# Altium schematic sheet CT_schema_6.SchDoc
size 368 x 245 mm
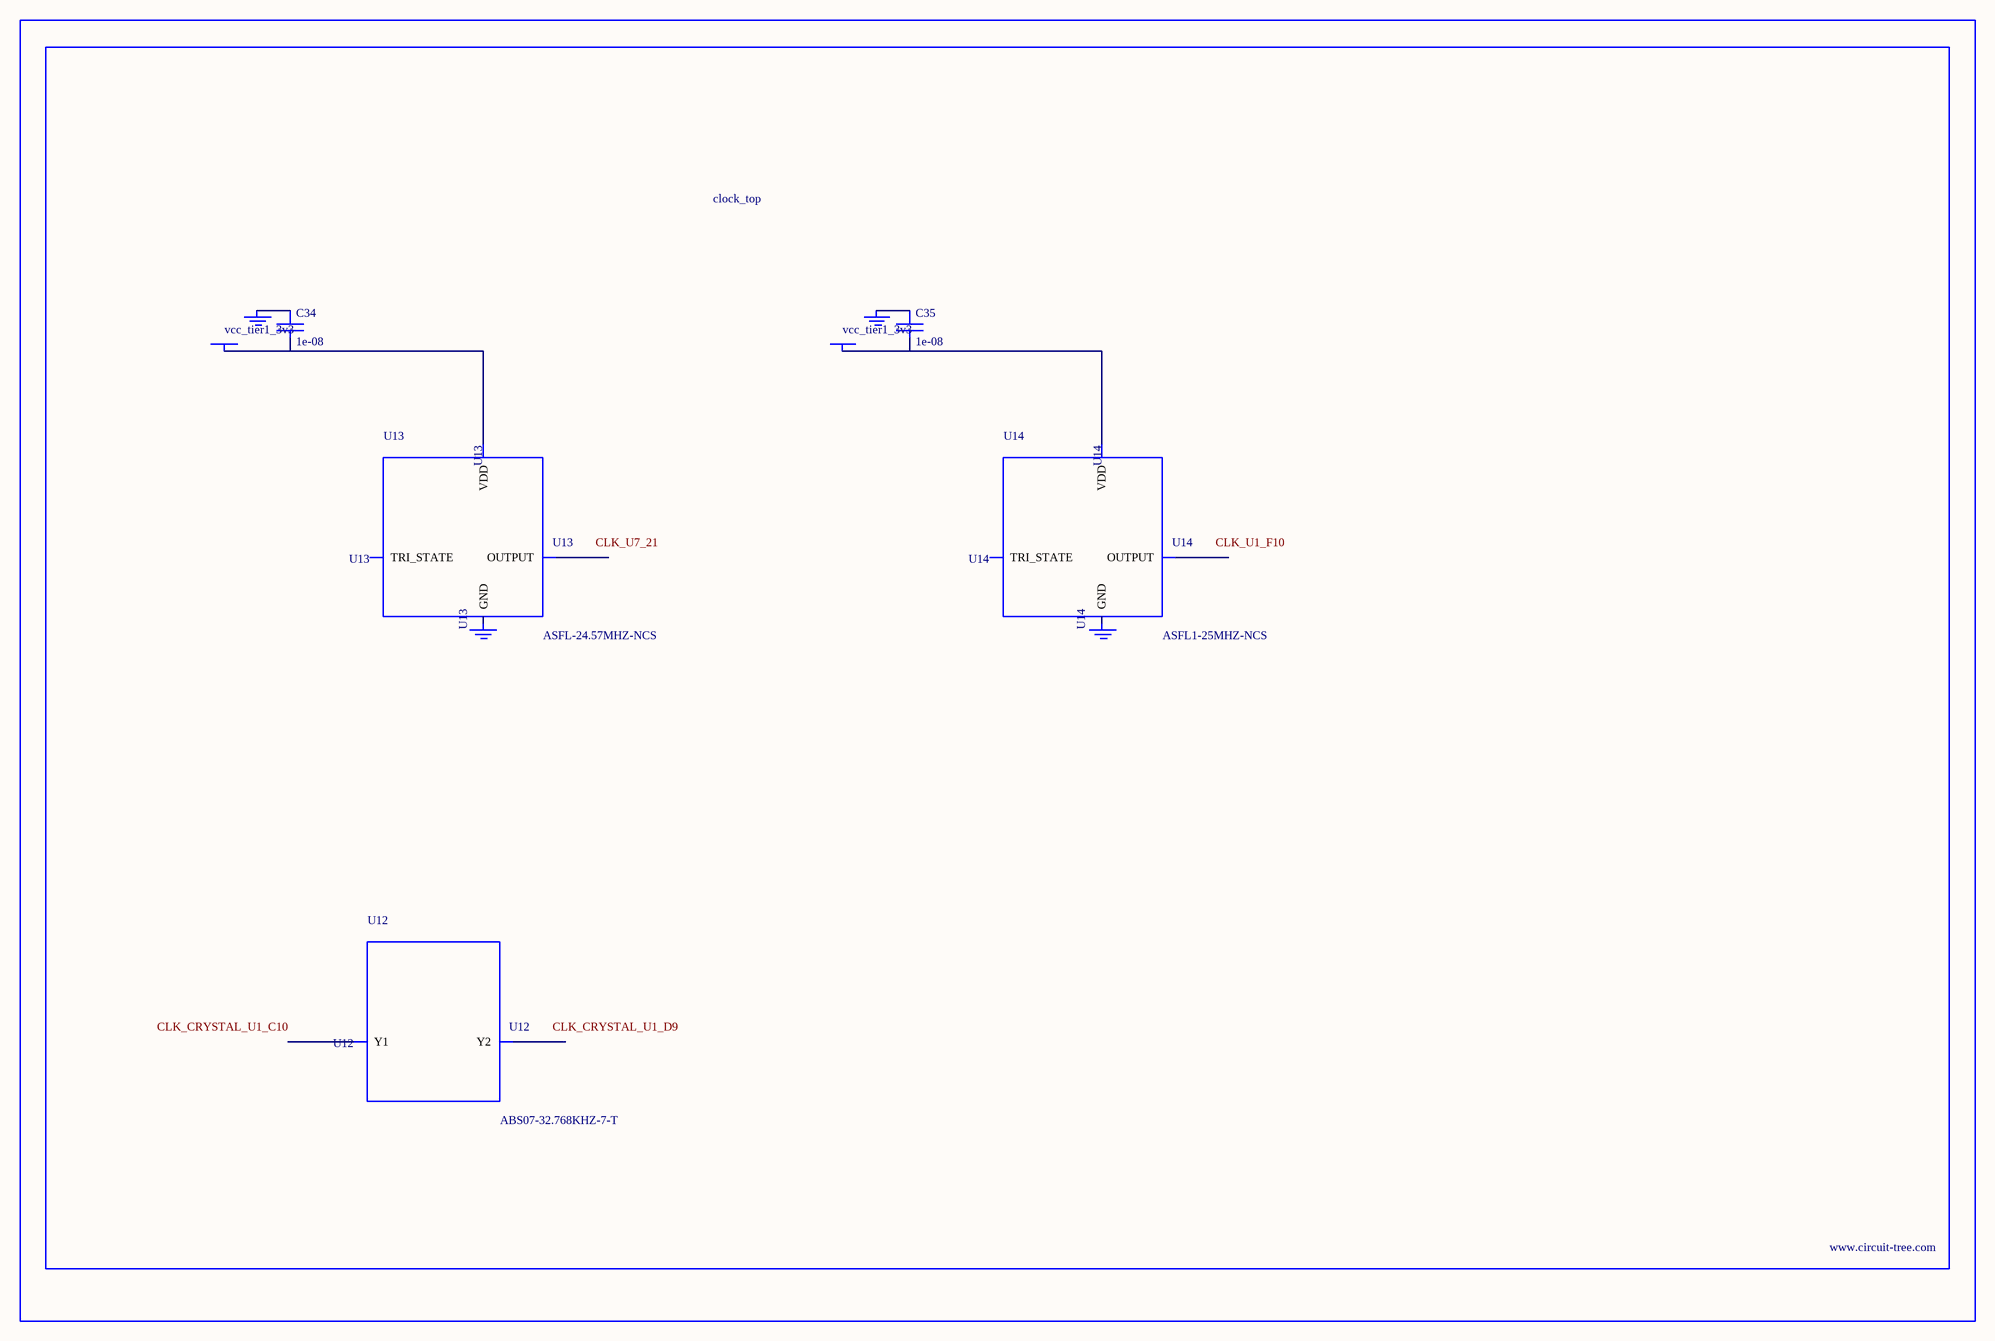
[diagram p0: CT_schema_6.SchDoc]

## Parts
BORDER5  (no value)
C34  1e-08  [C0402]
C35  1e-08  [C0402]
GND_INSTANCE_5_0  (no value)
GND_INSTANCE_5_1  (no value)
GND_INSTANCE_5_2  (no value)
GND_INSTANCE_5_3  (no value)
POWER_INSTANCE_5_0  vcc_tier1_3v3
POWER_INSTANCE_5_1  vcc_tier1_3v3
U12  ABS07-32.768KHZ-7-T  [ABS07-32.768KHZ-7-T]
U13  ASFL-24.57MHZ-NCS  [ASFL1]
U14  ASFL1-25MHZ-NCS  [ASFL1]

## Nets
NetC34_1: C34.1 GND_INSTANCE_5_0.0(GND)
NetC34_2: C34.2 POWER_INSTANCE_5_0.0(PWR) U13.4(VDD)
NetC35_1: C35.1 GND_INSTANCE_5_2.0(GND)
NetC35_2: C35.2 POWER_INSTANCE_5_1.0(PWR) U14.4(VDD)

Not connected (* = marked no-connect by the designer): GND_INSTANCE_5_1 0(GND); GND_INSTANCE_5_3 0(GND); U12 1(Y1) 2(Y2); U13 1(TRI_STATE) 2(GND) 3(OUTPUT); U14 1(TRI_STATE) 2(GND) 3(OUTPUT)

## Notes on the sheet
- Labels drawn without touching a wire or pin: CLK_CRYSTAL_U1_C10, CLK_CRYSTAL_U1_D9, CLK_U1_F10, CLK_U7_21

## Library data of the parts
BORDER5 = BORDER_PAGE5
C34 C35 = C0402C103K3RAC
GND_INSTANCE_5_0-GND_INSTANCE_5_3 = GND
POWER_INSTANCE_5_0 POWER_INSTANCE_5_1 = PWR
